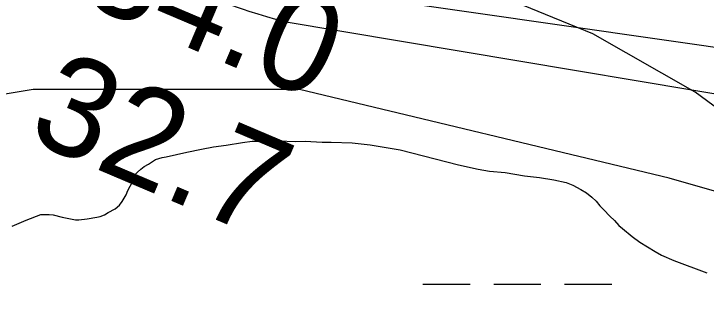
# Model space of a CAD drawing. Extents: x 3281947 to 3319794, y 715894 to 741249.
# Drawn here: x 3298149.1 to 3298618.1, y 727373.4 to 727566.6 of the extents above; entities that cross this region are included whole.
import ezdxf

# ---------------------------------------------------------------- set-up
doc = ezdxf.new("R2010")
doc.units = 0
for name, color, linetype in [('V-RIVR-RANG', 7, 'Continuous'), ('V-ROAD-CNTR', 7, 'Continuous'), ('V-SITE-VEGE', 7, 'Continuous'), ('V-TOPO-MAJR', 7, 'Continuous'), ('V-TOPO-MINR', 7, 'Continuous'), ('V-WETL-SWMP', 7, 'Continuous')]:
    doc.layers.add(name, color=color, linetype=linetype)

msp = doc.modelspace()

# ---------------------------------------------------------------- linework, layer by layer
at = {"layer": 'V-ROAD-CNTR'}
msp.add_lwpolyline([(3299107.31, 727470.94), (3299063.38, 727464.29), (3298994.49, 727466.7), (3298947.45, 727468.58), (3298896.35, 727467.7), (3298836.05, 727447.03), (3298798.89, 727440.8), (3298734.28, 727454.25), (3298644.03, 727488.91), (3298610.7, 727513.58), (3298541.45, 727553.09), (3298472.28, 727581.57), (3298420.91, 727594.24), (3298382.36, 727596.59), (3298349.24, 727593.7)], dxfattribs=at)
at = {"layer": 'V-SITE-VEGE'}
msp.add_lwpolyline([(3298147.87, 727422.84), (3298157.42, 727426.92), (3298167.37, 727430.79), (3298172.92, 727430.74), (3298175.69, 727430.52), (3298181.82, 727428.88), (3298190.93, 727427.21), (3298193.11, 727427.19), (3298198.66, 727427.73), (3298205.22, 727428.86), (3298207.6, 727429.44), (3298210.39, 727430.6), (3298212.98, 727432.17), (3298217.76, 727434.5), (3298220.56, 727437.05), (3298222.56, 727439.61), (3298225.18, 727444.15), (3298226.39, 727446.91), (3298229.42, 727452.83), (3298230.44, 727455.6), (3298231.25, 727457.78), (3298232.85, 727459.35), (3298235.05, 727461.51), (3298237.44, 727463.27), (3298240.23, 727464.83), (3298245.02, 727467.96), (3298249.59, 727469.31), (3298252.37, 727469.68), (3298266.28, 727472.92), (3298276.21, 727475.02), (3298284.35, 727476.53), (3298292.89, 727477.64), (3298304, 727479.52), (3298310.56, 727480.45), (3298317.89, 727480.39), (3298328.2, 727480.69), (3298340.09, 727480.19), (3298346.44, 727480.33), (3298357.93, 727479.83), (3298364.08, 727479.77), (3298378.35, 727479.25), (3298390.43, 727477.95), (3298410.82, 727474.6), (3298450.38, 727464.33), (3298463.64, 727461.43), (3298471.36, 727460.18), (3298481.86, 727459.09), (3298495.12, 727456.99), (3298505.22, 727455.7), (3298514.92, 727454.23), (3298523.23, 727452.37), (3298527.77, 727450.55), (3298533.3, 727447.72), (3298537.04, 727445.31), (3298540.59, 727442.5), (3298543.54, 727439.7), (3298546.09, 727436.7), (3298548.83, 727433.9), (3298552.76, 727429.51), (3298555.91, 727426.7), (3298559.05, 727423.3), (3298561.41, 727421.3), (3298568.1, 727415.89), (3298573.23, 727412.07), (3298583.48, 727405.64), (3298587.81, 727403.22), (3298596.31, 727399.58), (3298618.64, 727391.24)], dxfattribs=at)
at = {"layer": 'V-TOPO-MAJR'}
msp.add_lwpolyline([(3298141.7, 727657.99), (3298165.78, 727649.41), (3298189.9, 727640.95), (3298214.08, 727632.67), (3298238.31, 727624.51), (3298272.92, 727612.99), (3298302.68, 727603.41), (3298332.56, 727594.23), (3298362.61, 727585.64), (3298392.79, 727577.45), (3299424.68, 727429.3)], dxfattribs=at)
at = {"layer": 'V-TOPO-MINR'}
msp.add_lwpolyline([(3297245.98, 727842.49), (3298272.09, 727580.27), (3298276.21, 727579.16), (3298280.3, 727577.97), (3298284.35, 727576.66), (3298288.38, 727575.27), (3298292.4, 727573.84), (3298296.43, 727572.44), (3298300.47, 727571.07), (3298304.51, 727569.73), (3298308.3, 727568.49), (3298314.26, 727566.6), (3298320.25, 727564.8), (3298326.27, 727563.11), (3298332.32, 727561.51), (3298768.78, 727488.25), (3299458.54, 727402.3)], dxfattribs=at)
at = {"layer": 'V-WETL-SWMP'}
for p, q in [((3298426.17, 727383.49), (3298458.17, 727383.49)), ((3298474.17, 727383.49), (3298506.17, 727383.49)), ((3298522.17, 727383.49), (3298554.17, 727383.49))]:
    msp.add_line(p, q, dxfattribs=at)
msp.add_lwpolyline([(3300106.84, 727272.52), (3300036.08, 727154.48), (3299965.93, 727114.36), (3299935.87, 727184.56), (3299915.83, 727274.82), (3299895.79, 727345.02), (3299765.52, 727375.1), (3299635.25, 727334.99), (3299494.96, 727345.02), (3299304.57, 727355.05), (3299224.4, 727355.05), (3299054.05, 727365.08), (3298903.74, 727365.08), (3298803.54, 727405.19), (3298733.39, 727415.22), (3298593.1, 727455.33), (3298342.58, 727515.51), (3298162.21, 727515.5), (3298102.09, 727505.47), (3298062.01, 727475.39), (3297941.76, 727445.3), (3297831.53, 727435.28), (3297671.2, 727505.47), (3297540.93, 727555.62)], dxfattribs=at)

# ---------------------------------------------------------------- texts
at = {"layer": 'V-RIVR-RANG'}
for s, p in [('34.0', (3298192.69, 727575.38)), ('32.7', (3298156.52, 727482.1))]:
    msp.add_text(s, height=67, rotation=337.0083, dxfattribs=at).set_placement(p)

doc.saveas('drawing.dxf')
